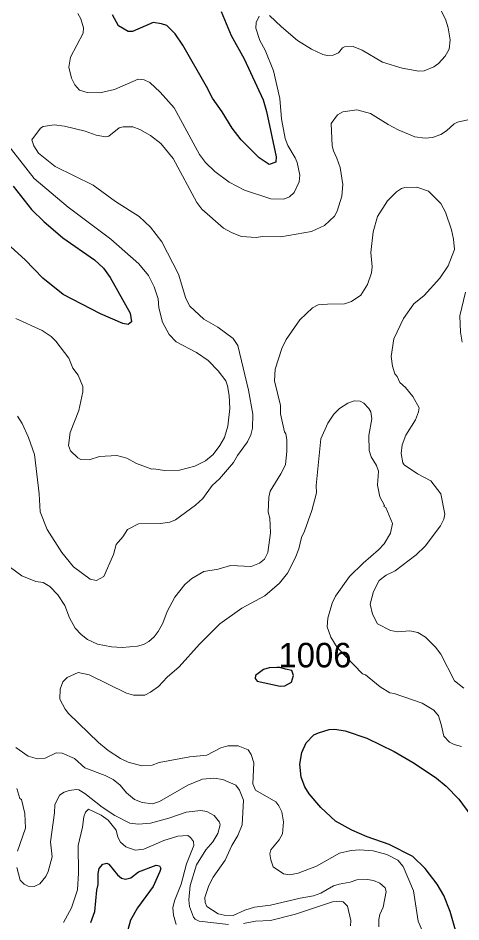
# Model space of a CAD drawing. Extents: x 447.8 to 473.9, y 7733.1 to 7760.8.
# Drawn here: x 454.635 to 456.079, y 7750.473 to 7753.422 of the extents above; entities that cross this region are included whole.
import ezdxf

# ---------------------------------------------------------------- set-up
doc = ezdxf.new("R2010")
doc.units = 0
doc.header["$LTSCALE"] = 0.032
doc.layers.add('1', color=7, linetype='Continuous', lineweight=25)
doc.layers.add('2', color=7, linetype='Continuous', lineweight=13)
doc.layers.add('21', color=7, linetype='Continuous')

msp = doc.modelspace()

# ---------------------------------------------------------------- linework, layer by layer
at = {"layer": '1'}
for points in [[(455.2968, 7753.4436), (455.3294, 7753.3655), (455.3721, 7753.2897), (455.4336, 7753.1557), (455.4449, 7753.1172), (455.4761, 7752.9693), (455.4758, 7752.9522), (455.4534, 7752.944), (455.4208, 7752.9659), (455.3621, 7753.025), (455.3325, 7753.0626), (455.3, 7753.1165), (455.2692, 7753.1604), (455.2497, 7753.1994), (455.1719, 7753.334), (455.1477, 7753.3704), (455.1202, 7753.3974), (455.103, 7753.4037), (455.0754, 7753.4078), (455.0079, 7753.3787), (454.994, 7753.3782), (454.9623, 7753.3973), (454.9431, 7753.433)], [(454.6191, 7752.8734), (454.6789, 7752.7976), (454.719, 7752.7581), (454.7806, 7752.7053), (454.8841, 7752.6338), (454.9132, 7752.6057), (454.935, 7752.576), (455.0009, 7752.4592), (455.0048, 7752.4315), (454.9936, 7752.4228), (454.9769, 7752.4261), (454.9042, 7752.457), (454.7818, 7752.5198), (454.7152, 7752.5736), (454.658, 7752.6333), (454.5263, 7752.7521)], [(456.0742, 7750.4008), (456.0436, 7750.5073), (456.0231, 7750.5591), (456.0016, 7750.5957), (455.9621, 7750.6476), (455.9221, 7750.687), (455.8453, 7750.7256), (455.7736, 7750.7508), (455.7227, 7750.7724), (455.6702, 7750.8019), (455.6226, 7750.8462), (455.5841, 7750.891), (455.5701, 7750.9138), (455.5579, 7750.9449), (455.5541, 7750.9875), (455.5598, 7751.0255), (455.5744, 7751.0574), (455.5994, 7751.083), (455.614, 7751.0904), (455.6494, 7751.1008), (455.6673, 7751.1016), (455.7019, 7751.0969), (455.7724, 7751.0722), (455.8609, 7751.0287), (455.926, 7750.9911), (455.9995, 7750.9417), (456.0303, 7750.9163), (456.0723, 7750.8735), (456.1112, 7750.8208)], [(454.8717, 7750.4716), (454.8853, 7750.5066), (454.8918, 7750.5771), (454.8966, 7750.5951), (454.8959, 7750.6307), (454.899, 7750.6476), (454.9111, 7750.6615), (454.9244, 7750.6647), (454.9306, 7750.6619), (454.9597, 7750.6266), (454.9726, 7750.6154), (454.9853, 7750.6128), (455.0029, 7750.6167), (455.0271, 7750.6365), (455.0848, 7750.6582), (455.0958, 7750.6561), (455.1001, 7750.6474), (455.0977, 7750.6378), (455.0751, 7750.5882), (455.0242, 7750.5192), (455.0015, 7750.4793), (454.9924, 7750.4467)]]:
    msp.add_lwpolyline(points, dxfattribs=at)
msp.add_lwpolyline([(455.4894, 7751.2428), (455.5052, 7751.2429), (455.5264, 7751.2551), (455.5334, 7751.2775), (455.5278, 7751.2929), (455.507, 7751.2982), (455.4886, 7751.3028), (455.4785, 7751.3035), (455.4532, 7751.3026), (455.4348, 7751.2965), (455.409, 7751.2772), (455.4082, 7751.2669), (455.4148, 7751.2587)], close=True, dxfattribs=at)
at = {"layer": '2'}
for points in [[(455.4549, 7753.431), (455.494, 7753.3931), (455.5458, 7753.3494), (455.5921, 7753.3202), (455.6284, 7753.3028), (455.6431, 7753.2997), (455.6627, 7753.3006), (455.6795, 7753.3083), (455.6932, 7753.3248), (455.6993, 7753.3282), (455.728, 7753.3299), (455.7566, 7753.3172), (455.8237, 7753.278), (455.8868, 7753.2582), (455.942, 7753.2484), (455.9592, 7753.25), (455.9907, 7753.2627), (456.0062, 7753.2742), (456.0279, 7753.2975), (456.0406, 7753.3207), (456.0437, 7753.3507), (456.0373, 7753.3908), (456.0287, 7753.4187), (455.9933, 7753.4868)], [(454.8296, 7753.4368), (454.8395, 7753.4198), (454.848, 7753.3902), (454.8477, 7753.3724), (454.8064, 7753.2942), (454.8006, 7753.2615), (454.8091, 7753.2261), (454.8203, 7753.2042), (454.8352, 7753.1873), (454.8608, 7753.1788), (454.9016, 7753.1778), (454.9491, 7753.1891), (455.0266, 7753.2223), (455.0458, 7753.221), (455.0643, 7753.2124), (455.0978, 7753.1808), (455.1436, 7753.1293), (455.2265, 7752.9767), (455.2462, 7752.9508), (455.2765, 7752.922)], [(455.5203, 7752.8392), (455.5353, 7752.8526), (455.5511, 7752.8882), (455.5536, 7752.9095), (455.5447, 7752.9509), (455.5388, 7752.9657), (455.5143, 7753.0068), (455.5061, 7753.029), (455.4939, 7753.0933), (455.4889, 7753.16), (455.4679, 7753.2502), (455.4409, 7753.317), (455.4229, 7753.3492), (455.4107, 7753.3896), (455.4118, 7753.4072), (455.4207, 7753.4288)], [(455.6762, 7753.1069), (455.6557, 7753.078), (455.6593, 7753.0048), (455.6629, 7752.9888), (455.6744, 7752.9655), (455.6847, 7752.9351), (455.6935, 7752.879), (455.6907, 7752.8416), (455.675, 7752.7925), (455.6669, 7752.7754), (455.6336, 7752.7451), (455.5913, 7752.7256), (455.4913, 7752.7081), (455.4319, 7752.7097), (455.4115, 7752.7057), (455.3639, 7752.7093), (455.3329, 7752.7211), (455.3046, 7752.7369), (455.2337, 7752.7984), (455.2182, 7752.82), (455.141, 7752.9636), (455.1004, 7753.0126), (455.0663, 7753.0395), (455.0324, 7753.059), (455.0096, 7753.0671), (454.9775, 7753.0672), (454.9645, 7753.0637), (454.9314, 7753.0366), (454.9203, 7753.0351), (454.8896, 7753.0403), (454.8538, 7753.0528), (454.7865, 7753.0696), (454.7524, 7753.0735), (454.7169, 7753.0683), (454.7078, 7753.0633), (454.6796, 7753.0254), (454.6864, 7753.0052), (454.7018, 7752.9812), (454.7554, 7752.9379), (454.8798, 7752.8771), (454.953, 7752.8238), (455.03, 7752.7743), (455.0668, 7752.7399), (455.1042, 7752.692), (455.1578, 7752.5865), (455.1818, 7752.5067), (455.1952, 7752.4819), (455.2408, 7752.4402), (455.2868, 7752.414), (455.3363, 7752.3772), (455.3511, 7752.3537), (455.3864, 7752.2078), (455.4, 7752.1297), (455.3992, 7752.0844), (455.3944, 7752.062), (455.3832, 7752.0396), (455.3505, 7751.9949), (455.3373, 7751.972), (455.2912, 7751.9187), (455.2683, 7751.8974), (455.2371, 7751.8549), (455.213, 7751.8333), (455.1485, 7751.7853), (455.1294, 7751.7778), (455.099, 7751.7727), (455.0272, 7751.7719), (454.9913, 7751.7539), (454.9762, 7751.7296), (454.9551, 7751.7049), (454.9461, 7751.6718), (454.9141, 7751.6), (454.8907, 7751.587), (454.8696, 7751.591), (454.8154, 7751.6319), (454.7774, 7751.6786), (454.7302, 7751.7536), (454.7075, 7751.8115), (454.7042, 7751.8699), (454.6882, 7751.9978), (454.6693, 7752.0533), (454.648, 7752.0991), (454.6335, 7752.1232)], [(455.874, 7753.0574), (455.8412, 7753.0745), (455.784, 7753.1112), (455.7398, 7753.1223), (455.6943, 7753.116), (455.6762, 7753.1069)], [(456.1018, 7753.0897), (456.0674, 7753.0822), (456.0571, 7753.0773), (456.0318, 7753.0543), (456.0129, 7753.0422), (455.986, 7753.033), (455.9624, 7753.0303), (455.9287, 7753.0346), (455.874, 7753.0574)], [(454.6276, 7752.4414), (454.7135, 7752.403), (454.7424, 7752.3837), (454.7584, 7752.3683), (454.8006, 7752.3129), (454.8132, 7752.2801), (454.8308, 7752.2566), (454.846, 7752.2202), (454.8458, 7752.2029), (454.8334, 7752.1412), (454.8049, 7752.0696), (454.7998, 7752.0273), (454.8064, 7752.0102), (454.8297, 7751.9868), (454.84, 7751.9814), (454.8673, 7751.981), (454.9006, 7751.9921), (454.9569, 7751.9953), (454.99, 7751.9858), (455.0215, 7751.9685), (455.0706, 7751.95), (455.0778, 7751.9512), (455.1123, 7751.9458), (455.1618, 7751.9466), (455.2114, 7751.9606), (455.2464, 7751.9771), (455.2707, 7751.9981), (455.2932, 7752.0277), (455.3081, 7752.0534), (455.3189, 7752.0909), (455.3254, 7752.148), (455.3237, 7752.1905), (455.3182, 7752.2218), (455.3124, 7752.2385), (455.2875, 7752.2713), (455.2551, 7752.3044), (455.2169, 7752.3314), (455.1508, 7752.3658), (455.1278, 7752.3898), (455.1054, 7752.4304), (455.0938, 7752.4772), (455.092, 7752.5066), (455.0784, 7752.5447), (455.0602, 7752.5826), (455.0286, 7752.6207), (454.9373, 7752.7009), (454.7983, 7752.805), (454.6872, 7752.8992), (454.566, 7753.0529)], [(455.2765, 7752.922), (455.3235, 7752.8866), (455.3734, 7752.8604), (455.459, 7752.8325), (455.5013, 7752.8318), (455.5203, 7752.8392)], [(455.8713, 7752.2527), (455.8636, 7752.261), (455.8554, 7752.2861), (455.8514, 7752.3174), (455.8605, 7752.3757), (455.8916, 7752.4422), (455.9257, 7752.4898), (455.9592, 7752.5169), (456.0102, 7752.5736), (456.0373, 7752.6142), (456.0574, 7752.6669), (456.055, 7752.701), (456.0482, 7752.7316), (456.0291, 7752.7885), (456.0132, 7752.817), (455.9729, 7752.8578), (455.9347, 7752.8699), (455.8959, 7752.8691), (455.8856, 7752.8662), (455.8692, 7752.8557), (455.8397, 7752.826), (455.8071, 7752.7742), (455.7926, 7752.7246), (455.7847, 7752.6572), (455.7896, 7752.6109), (455.7872, 7752.5907), (455.7746, 7752.5532), (455.7522, 7752.5185), (455.7219, 7752.4971), (455.6988, 7752.4893), (455.6439, 7752.4892), (455.613, 7752.4861), (455.5944, 7752.4766), (455.5531, 7752.4379), (455.5092, 7752.3732), (455.4952, 7752.3435), (455.473, 7752.2771), (455.4714, 7752.2389), (455.4906, 7752.1581), (455.4907, 7752.1309), (455.5035, 7752.0718), (455.5083, 7752.066), (455.5114, 7752.0475), (455.5114, 7752.0091), (455.5074, 7751.9645), (455.4922, 7751.9353), (455.4572, 7751.8782), (455.4522, 7751.8586), (455.4506, 7751.8099), (455.4554, 7751.7904), (455.4585, 7751.7423), (455.4498, 7751.6785), (455.4387, 7751.6566), (455.4226, 7751.6432), (455.3947, 7751.6332), (455.3274, 7751.6356), (455.2876, 7751.6241), (455.2408, 7751.6163), (455.202, 7751.5938), (455.1786, 7751.5744), (455.1463, 7751.5327), (455.121, 7751.4864), (455.1065, 7751.4479), (455.0922, 7751.4208), (455.0784, 7751.4036), (455.0608, 7751.388), (455.0439, 7751.3785), (455.0244, 7751.3727), (454.9749, 7751.3687), (454.9401, 7751.3703), (454.8936, 7751.3796), (454.8611, 7751.3947), (454.8402, 7751.4108), (454.8216, 7751.432), (454.803, 7751.4654), (454.787, 7751.5054), (454.7645, 7751.5407), (454.7382, 7751.568), (454.7169, 7751.5807), (454.6928, 7751.5833), (454.6474, 7751.6018), (454.6105, 7751.6299)], [(456.0826, 7752.3651), (456.0778, 7752.3975), (456.0758, 7752.4511), (456.0933, 7752.5278)], [(455.941, 7752.137), (455.9427, 7752.1508), (455.9222, 7752.1876), (455.8979, 7752.2164), (455.8802, 7752.2328), (455.8713, 7752.2527)], [(455.6447, 7752.1007), (455.665, 7752.1298), (455.6828, 7752.1482), (455.7103, 7752.1654), (455.7312, 7752.1733), (455.75, 7752.1718), (455.7618, 7752.1659), (455.7791, 7752.1485), (455.7856, 7752.137), (455.7881, 7752.1147), (455.7784, 7752.0606), (455.7793, 7752.0116), (455.7867, 7751.9907), (455.8031, 7751.9628), (455.8096, 7751.9433), (455.8072, 7751.8976), (455.8144, 7751.8604), (455.8293, 7751.8315), (455.8277, 7751.8286), (455.8338, 7751.8253), (455.8553, 7751.7734), (455.8496, 7751.741), (455.8284, 7751.707), (455.8102, 7751.6866), (455.7597, 7751.6441), (455.7161, 7751.6005), (455.6698, 7751.5355), (455.6588, 7751.5134), (455.645, 7751.4638), (455.643, 7751.4358), (455.6552, 7751.4025), (455.6753, 7751.3684), (455.7583, 7751.2828), (455.7678, 7751.2788), (455.8155, 7751.2396), (455.8468, 7751.2203), (455.8617, 7751.2179), (455.9526, 7751.1865), (455.9903, 7751.1639), (456.0056, 7751.1455), (456.0148, 7751.1177), (456.0229, 7751.0793), (456.0417, 7751.0598), (456.0573, 7751.0516), (456.0802, 7751.0456)], [(456.0887, 7751.2363), (456.0581, 7751.2599), (456.0136, 7751.3463), (455.9962, 7751.3697), (455.9629, 7751.4027), (455.9386, 7751.4172), (455.9119, 7751.4231), (455.873, 7751.42), (455.8493, 7751.4244), (455.8067, 7751.4455), (455.791, 7751.4769), (455.7832, 7751.5096), (455.7936, 7751.5512), (455.8128, 7751.5871), (455.8354, 7751.6042), (455.8644, 7751.6189), (455.9329, 7751.6706), (455.9624, 7751.6993), (456.012, 7751.7659), (456.0227, 7751.7875), (456.0259, 7751.8033), (456.0132, 7751.8703), (455.9803, 7751.912), (455.9376, 7751.9347), (455.894, 7751.9641), (455.8897, 7751.9711), (455.8843, 7752.0016), (455.887, 7752.0294), (455.8991, 7752.0613), (455.9311, 7752.111), (455.941, 7752.137)], [(455.7924, 7750.7049), (455.7497, 7750.7081), (455.7211, 7750.7057), (455.6833, 7750.6977), (455.6076, 7750.6551), (455.5477, 7750.6318), (455.5205, 7750.6272), (455.5003, 7750.6296), (455.4666, 7750.653), (455.4589, 7750.6754), (455.4562, 7750.6949), (455.4588, 7750.7083), (455.4864, 7750.7407), (455.497, 7750.76), (455.5002, 7750.7993), (455.4947, 7750.832), (455.4857, 7750.8523), (455.4756, 7750.8651), (455.4092, 7750.9027), (455.4, 7750.9241), (455.4039, 7750.9917), (455.3947, 7751.0193), (455.3849, 7751.0341), (455.3524, 7751.0472), (455.3194, 7751.0472), (455.2963, 7751.0414), (455.2506, 7751.0168), (455.1953, 7751.0119), (455.0953, 7750.9928), (455.0719, 7750.9846), (455.0389, 7750.9823), (454.9936, 7750.9942), (454.9689, 7751.0067), (454.929, 7751.0327), (454.8969, 7751.059), (454.7999, 7751.1535), (454.789, 7751.167), (454.7709, 7751.1998), (454.7722, 7751.232), (454.7809, 7751.2561), (454.7949, 7751.2707), (454.8314, 7751.2867), (454.8671, 7751.2797), (454.9885, 7751.2197), (455.0109, 7751.2132), (455.0479, 7751.2132), (455.0673, 7751.2224), (455.093, 7751.2413), (455.1216, 7751.2721), (455.1601, 7751.3057), (455.226, 7751.3797), (455.2924, 7751.446), (455.3645, 7751.4964), (455.4399, 7751.5371), (455.4875, 7751.5779), (455.5134, 7751.6113), (455.5389, 7751.6598), (455.55, 7751.6903), (455.5593, 7751.7279), (455.5692, 7751.748), (455.5933, 7751.8153), (455.6076, 7751.8729), (455.6072, 7751.8973), (455.622, 7752.0488), (455.6447, 7752.1007)], [(454.6272, 7751.0418), (454.6678, 7751.0135), (454.698, 7751.0047), (454.7237, 7751.0077), (454.7596, 7751.0247), (454.7788, 7751.0239), (454.8192, 7751.0068), (454.8532, 7750.9763), (454.9193, 7750.9512), (454.9445, 7750.9378), (454.9682, 7750.9195), (454.9889, 7750.8939), (455.0142, 7750.8729), (455.0392, 7750.8624), (455.0728, 7750.8589), (455.096, 7750.8659), (455.1885, 7750.9197), (455.236, 7750.939), (455.2737, 7750.9422), (455.3027, 7750.9374), (455.3447, 7750.9189), (455.3565, 7750.9034), (455.3703, 7750.8704), (455.3655, 7750.79), (455.351, 7750.7552), (455.3321, 7750.7228), (455.3097, 7750.6742), (455.2711, 7750.6186), (455.2567, 7750.5921), (455.2438, 7750.5524), (455.2451, 7750.5367), (455.2502, 7750.523), (455.2877, 7750.4994), (455.3073, 7750.4947), (455.3367, 7750.4943), (455.3747, 7750.5118), (455.4059, 7750.5214), (455.4575, 7750.5275), (455.555, 7750.551), (455.5985, 7750.5579), (455.6223, 7750.5664), (455.6632, 7750.5906), (455.6817, 7750.5967), (455.7175, 7750.6024), (455.7391, 7750.6103), (455.7743, 7750.6119), (455.7938, 7750.6086), (455.8144, 7750.599), (455.8318, 7750.5838), (455.8346, 7750.5722), (455.8256, 7750.5216), (455.8144, 7750.4969), (455.8113, 7750.4812), (455.8114, 7750.4571)], [(454.6311, 7750.9084), (454.6412, 7750.8763), (454.6457, 7750.8729), (454.657, 7750.8272), (454.6593, 7750.7791), (454.6331, 7750.7035)], [(454.6314, 7750.6501), (454.6414, 7750.6094), (454.6554, 7750.596), (454.6684, 7750.5893), (454.6877, 7750.5887), (454.7056, 7750.5973), (454.7253, 7750.621), (454.7332, 7750.6376), (454.7466, 7750.6856), (454.7412, 7750.734), (454.7539, 7750.8288), (454.7548, 7750.855), (454.7705, 7750.8864), (454.785, 7750.8963), (454.8015, 7750.9021), (454.8253, 7750.9052), (454.8333, 7750.9036), (454.8528, 7750.8922), (454.9095, 7750.847), (454.9501, 7750.8202), (454.9997, 7750.7955)], [(455.1503, 7750.4647), (455.1419, 7750.4956), (455.1396, 7750.5188), (455.1447, 7750.5415), (455.1665, 7750.5963), (455.184, 7750.6629), (455.208, 7750.7227), (455.2066, 7750.7358), (455.1977, 7750.748), (455.1887, 7750.755), (455.1559, 7750.7529), (455.1098, 7750.7382), (455.0447, 7750.7102), (455.0172, 7750.7075), (454.9863, 7750.7182), (454.9688, 7750.7334), (454.9601, 7750.7497), (454.9546, 7750.772), (454.9292, 7750.8052), (454.9059, 7750.8212), (454.8646, 7750.8405), (454.8549, 7750.831), (454.8494, 7750.8162), (454.8452, 7750.7827), (454.8312, 7750.7226), (454.8317, 7750.6324), (454.8284, 7750.5773), (454.809, 7750.5195), (454.7833, 7750.4712)], [(454.9997, 7750.7955), (455.0278, 7750.7915), (455.0663, 7750.7952), (455.1262, 7750.8111), (455.1831, 7750.8316), (455.2309, 7750.8371)], [(455.2309, 7750.8371), (455.2499, 7750.8331), (455.2738, 7750.8198), (455.2917, 7750.7986), (455.2935, 7750.7898), (455.2864, 7750.7618), (455.2695, 7750.7348), (455.2472, 7750.7088), (455.2166, 7750.6595), (455.1957, 7750.5921), (455.1916, 7750.5448), (455.194, 7750.5232), (455.2074, 7750.4884), (455.2128, 7750.4824), (455.2255, 7750.4759), (455.3212, 7750.4645)], [(455.9394, 7750.4755), (455.9238, 7750.5747), (455.89, 7750.6542), (455.8729, 7750.6744), (455.8372, 7750.6927), (455.7924, 7750.7049)], [(455.3703, 7750.4677), (455.4088, 7750.4756), (455.4576, 7750.4774), (455.5397, 7750.4987), (455.6602, 7750.5389), (455.6843, 7750.5413), (455.695, 7750.5389), (455.7094, 7750.5245), (455.7199, 7750.4772), (455.7189, 7750.4598)], [(455.9586, 7750.4302), (455.9394, 7750.4755)]]:
    msp.add_lwpolyline(points, dxfattribs=at)

# ---------------------------------------------------------------- texts
at = {"layer": '21'}
msp.add_text('1006', height=0.08, dxfattribs=at).set_placement((455.4841, 7751.3036))

doc.saveas('drawing.dxf')
